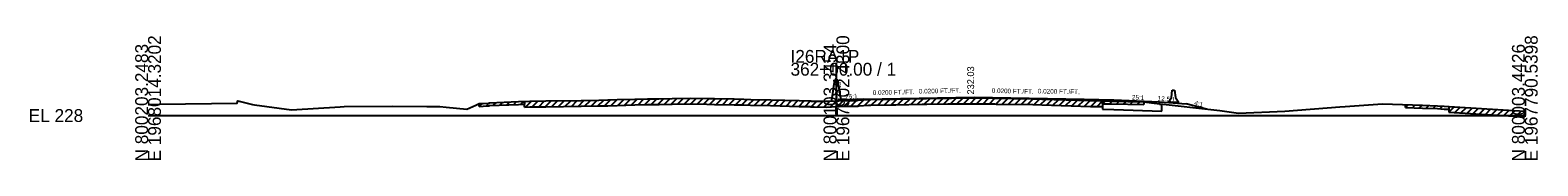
# Model space of a CAD drawing. Extents: x -26 to 304, y -10 to 7527.
# Drawn here: x -25.7 to 302.8, y 5990.3 to 6017.3 of the extents above; entities that cross this region are included whole.
import ezdxf

# ---------------------------------------------------------------- set-up
doc = ezdxf.new("R2010")
doc.units = 0
for name, color, linetype in [('Default', 7, 'Continuous'), ('RD_GPK_XS_Cell', 7, 'Continuous'), ('RD_XS_Base', 7, 'Continuous'), ('RD_XS_Box', 7, 'Continuous'), ('RD_XS_EarthShd', 7, 'Continuous'), ('RD_XS_ExGround', 7, 'Continuous'), ('RD_XS_ExPaveRet', 7, 'Continuous'), ('RD_XS_Misc_Line', 7, 'Continuous'), ('RD_XS_Pave', 7, 'Continuous'), ('RD_XS_PaveShd', 7, 'Continuous'), ('RD_XS_TX_Elev_EX', 7, 'Continuous'), ('RD_XS_TX_Elev_PR', 7, 'Continuous'), ('RD_XS_TX_Misc', 7, 'Continuous'), ('RD_XS_TX_MkPT', 7, 'Continuous'), ('RD_XS_TX_Profile', 7, 'Continuous'), ('RD_XS_TX_Station', 7, 'Continuous')]:
    doc.layers.add(name, color=color, linetype=linetype)

msp = doc.modelspace()

# ---------------------------------------------------------------- linework, layer by layer
at = {"layer": 'Default'}
for p, q in [((222.43, 6003.08), (223.01, 6003.92)), ((222.43, 6002.83), (222.43, 6003.08)), ((224.43, 6002.83), (222.43, 6002.83)), ((223.01, 6003.92), (223.18, 6005.5)), ((223.18, 6005.5), (223.68, 6005.5)), ((223.68, 6005.5), (223.85, 6003.92)), ((223.85, 6003.92), (224.43, 6003.08)), ((224.43, 6003.08), (224.43, 6002.83))]:
    msp.add_line(p, q, dxfattribs=at)
at = {"layer": 'RD_GPK_XS_Cell'}
for p, q in [((150, 6000), (150, 6011.49)), ((0, 6000), (150, 6000)), ((150, 6000), (300, 6000))]:
    msp.add_line(p, q, dxfattribs=at)
at = {"layer": 'RD_XS_Base'}
for p, q in [((150, 6003.19), (150, 6003.31)), ((220.43, 6002.43), (220.43, 6002.99)), ((220.93, 6002.41), (220.43, 6002.43)), ((220.93, 6000.93), (220.93, 6002.41)), ((208, 6001.41), (210.42, 6001.35)), ((210.42, 6001.35), (220.93, 6000.93))]:
    msp.add_line(p, q, dxfattribs=at)
at = {"layer": 'RD_XS_Box'}
for p in [(222.43, 6002.83), (230.67, 6001.41)]:
    msp.add_line(p, (226.18, 6002.53), dxfattribs=at)
at = {"layer": 'RD_XS_EarthShd'}
for p, q in [((149, 6003.33), (149.67, 6007.81)), ((150, 6007.81), (149.67, 6007.81)), ((150, 6007.81), (150.33, 6007.81)), ((151, 6003.33), (150.33, 6007.81)), ((220.43, 6002.99), (222.43, 6002.83))]:
    msp.add_line(p, q, dxfattribs=at)
at = {"layer": 'RD_XS_ExGround'}
msp.add_lwpolyline([(0, 6002.43), (0.97, 6002.44), (2.54, 6002.46), (19.43, 6002.68), (19.53, 6003.18), (22.76, 6002.44), (23.22, 6002.36), (31.22, 6001.28), (41.89, 6001.91), (42.73, 6001.96), (53.35, 6002.05), (60.75, 6001.98), (63.6, 6001.95), (64.95, 6001.82), (69.49, 6001.41), (71.44, 6002.26), (72.16, 6002.6), (72.99, 6002.64), (74.23, 6002.7), (74.41, 6002.8), (80.74, 6003.05), (83.18, 6003.14), (86.7, 6003.18), (94.34, 6003.26), (98.21, 6003.35), (100.16, 6003.39), (102.2, 6003.46), (106.07, 6003.59), (108.84, 6003.62), (111.33, 6003.64), (114.17, 6003.7), (118.15, 6003.79), (121.8, 6003.71), (123.44, 6003.68), (127.71, 6003.61), (129.82, 6003.57), (131.33, 6003.53), (135.68, 6003.41), (141.9, 6003.25), (144.41, 6003.18), (144.6, 6003.14), (145.19, 6003.13), (147.82, 6003.1), (150, 6003.19), (150.51, 6003.22), (151.78, 6003.27), (152.21, 6003.28), (154.41, 6003.31), (154.64, 6003.38), (156.92, 6003.48), (157.49, 6003.5), (161.97, 6003.57), (162.93, 6003.59), (168.63, 6003.72), (169.08, 6003.73), (169.66, 6003.74), (174.23, 6003.78), (174.66, 6003.78), (175.06, 6003.78), (181.03, 6003.83), (184.47, 6003.77), (184.83, 6003.76), (192.81, 6003.62), (194.77, 6003.56), (205.37, 6003.25), (209.92, 6003.15), (216.95, 6003), (219.2, 6002.73), (233.51, 6001.08), (237.6, 6000.5), (247.74, 6000.97), (259.67, 6001.92), (260.87, 6002), (268.99, 6002.55), (277.73, 6002.25), (281.01, 6002.15), (282.45, 6002.05), (284.65, 6001.91), (300, 6000.98)], dxfattribs=at)
at = {"layer": 'RD_XS_ExPaveRet'}
for p, q in [((72.16, 6001.97), (72.16, 6002.6)), ((74.41, 6002.18), (80.74, 6002.43)), ((80.74, 6002.43), (82, 6002.48)), ((82, 6001.85), (82, 6003.1)), ((82, 6003.1), (82, 6002.48)), ((208, 6003.19), (208, 6001.94)), ((208, 6002.57), (208, 6003.19)), ((208, 6002.57), (209.92, 6002.53)), ((209.92, 6002.53), (216.95, 6002.38)), ((216.95, 6003), (216.95, 6002.38)), ((274.01, 6001.75), (274.01, 6002.38)), ((72.16, 6001.97), (72.99, 6002.02)), ((72.99, 6002.02), (74.23, 6002.08)), ((74.23, 6002.08), (74.41, 6002.18)), ((274.01, 6001.75), (277.73, 6001.63)), ((277.73, 6001.63), (281.01, 6001.52)), ((281.01, 6001.52), (282.45, 6001.42)), ((282.45, 6001.42), (283.43, 6001.36)), ((283.43, 6001.99), (283.43, 6000.74)), ((300, 6000.98), (300, 5999.73))]:
    msp.add_line(p, q, dxfattribs=at)
for points in [[(82, 6001.85), (83.21, 6001.89), (86.71, 6001.93), (94.36, 6002.01), (98.24, 6002.1), (100.2, 6002.14), (102.24, 6002.21), (106.1, 6002.34), (108.85, 6002.37), (111.35, 6002.39), (114.19, 6002.45), (118.15, 6002.54), (121.77, 6002.46), (123.42, 6002.43), (127.69, 6002.36), (129.79, 6002.33), (131.3, 6002.28), (135.65, 6002.16), (141.87, 6002), (144.25, 6001.94), (144.45, 6001.89), (145.18, 6001.88), (147.84, 6001.85), (150.06, 6001.94), (150.56, 6001.97), (151.82, 6002.02), (152.24, 6002.03), (154.63, 6002.06), (154.87, 6002.14), (156.97, 6002.23), (157.52, 6002.25), (161.99, 6002.32), (162.95, 6002.34), (168.66, 6002.47), (169.1, 6002.48), (169.67, 6002.49), (174.24, 6002.53), (174.67, 6002.53), (175.06, 6002.53), (181.02, 6002.58), (184.45, 6002.52), (184.81, 6002.51), (192.78, 6002.37), (194.73, 6002.31), (205.34, 6002), (208, 6001.94)], [(283.43, 6000.74), (284.58, 6000.67), (300, 5999.73)]]:
    msp.add_lwpolyline(points, dxfattribs=at)
at = {"layer": 'RD_XS_Misc_Line'}
for p, q in [((72.16, 6001.97), (72.82, 6002.63)), ((73.66, 6002.05), (74.42, 6002.81)), ((75.16, 6002.21), (75.82, 6002.86)), ((76.66, 6002.27), (77.32, 6002.92)), ((78.17, 6002.33), (78.82, 6002.98)), ((79.67, 6002.39), (80.32, 6003.04)), ((81.17, 6002.44), (81.81, 6003.09)), ((82, 6003.04), (82.07, 6003.1)), ((82.24, 6001.86), (83.53, 6003.15)), ((83.69, 6001.9), (84.95, 6003.16)), ((85.12, 6001.91), (86.38, 6003.18)), ((86.55, 6001.93), (87.81, 6003.19)), ((87.98, 6001.94), (89.24, 6003.21)), ((89.41, 6001.96), (90.67, 6003.22)), ((90.83, 6001.97), (92.1, 6003.23)), ((92.26, 6001.99), (93.52, 6003.25)), ((93.69, 6002), (94.96, 6003.27)), ((95.13, 6002.02), (96.41, 6003.3)), ((96.58, 6002.06), (97.86, 6003.34)), ((98.02, 6002.09), (99.31, 6003.37)), ((99.47, 6002.13), (100.76, 6003.41)), ((100.93, 6002.17), (102.22, 6003.46)), ((102.39, 6002.21), (103.68, 6003.51)), ((103.85, 6002.26), (105.15, 6003.56)), ((105.32, 6002.31), (106.6, 6003.59)), ((106.77, 6002.35), (108.03, 6003.61)), ((108.2, 6002.36), (109.46, 6003.63)), ((109.62, 6002.38), (110.89, 6003.64)), ((111.05, 6002.39), (112.32, 6003.66)), ((112.49, 6002.41), (113.77, 6003.69)), ((113.93, 6002.44), (115.21, 6003.72)), ((115.38, 6002.47), (116.66, 6003.75)), ((116.82, 6002.51), (118.1, 6003.78)), ((118.27, 6002.53), (119.49, 6003.76)), ((119.65, 6002.51), (120.88, 6003.73)), ((121.04, 6002.48), (122.27, 6003.7)), ((122.43, 6002.45), (123.65, 6003.68)), ((123.82, 6002.43), (125.05, 6003.66)), ((125.21, 6002.4), (126.44, 6003.63)), ((126.6, 6002.38), (127.83, 6003.61)), ((127.99, 6002.36), (129.22, 6003.59)), ((129.38, 6002.33), (130.6, 6003.55)), ((130.76, 6002.3), (131.98, 6003.52)), ((132.14, 6002.26), (133.35, 6003.48)), ((133.51, 6002.22), (134.73, 6003.44)), ((134.89, 6002.19), (136.11, 6003.4)), ((136.27, 6002.15), (137.48, 6003.37)), ((137.64, 6002.11), (138.86, 6003.33)), ((139.02, 6002.07), (140.24, 6003.29)), ((140.4, 6002.04), (141.62, 6003.26)), ((141.78, 6002), (142.99, 6003.22)), ((143.15, 6001.96), (144.37, 6003.18)), ((144.49, 6001.89), (145.72, 6003.12)), ((145.89, 6001.87), (147.12, 6003.1)), ((147.28, 6001.85), (148.56, 6003.13)), ((148.73, 6001.89), (150.04, 6003.2)), ((150.21, 6001.95), (151.52, 6003.26)), ((151.69, 6002.01), (152.96, 6003.29)), ((153.13, 6002.04), (154.39, 6003.31)), ((154.56, 6002.06), (155.94, 6003.44)), ((156.11, 6002.19), (157.41, 6003.49)), ((157.58, 6002.25), (158.85, 6003.52)), ((159.02, 6002.27), (160.29, 6003.54)), ((160.46, 6002.3), (161.73, 6003.57)), ((161.89, 6002.32), (163.17, 6003.6)), ((163.34, 6002.35), (164.62, 6003.63)), ((164.79, 6002.38), (166.07, 6003.66)), ((166.23, 6002.42), (167.51, 6003.7)), ((167.68, 6002.45), (168.96, 6003.73)), ((169.13, 6002.48), (170.39, 6003.74)), ((170.55, 6002.49), (171.82, 6003.76)), ((171.98, 6002.51), (173.24, 6003.77)), ((173.41, 6002.52), (174.67, 6003.78)), ((174.84, 6002.53), (176.09, 6003.79)), ((176.26, 6002.54), (177.52, 6003.8)), ((177.68, 6002.55), (178.94, 6003.81)), ((179.11, 6002.57), (180.37, 6003.83)), ((180.54, 6002.58), (181.78, 6003.82)), ((181.94, 6002.56), (183.16, 6003.79)), ((183.33, 6002.54), (184.55, 6003.77)), ((184.71, 6002.51), (185.94, 6003.74)), ((186.1, 6002.49), (187.33, 6003.72)), ((187.49, 6002.46), (188.72, 6003.69)), ((188.88, 6002.44), (190.11, 6003.67)), ((190.27, 6002.41), (191.5, 6003.64)), ((191.66, 6002.39), (192.89, 6003.61)), ((193.04, 6002.36), (194.26, 6003.57)), ((194.42, 6002.32), (195.63, 6003.53)), ((195.79, 6002.28), (197.01, 6003.49)), ((197.17, 6002.24), (198.38, 6003.45)), ((198.54, 6002.2), (199.76, 6003.42)), ((199.92, 6002.16), (201.13, 6003.38)), ((201.29, 6002.12), (202.51, 6003.34)), ((202.67, 6002.08), (203.88, 6003.3)), ((204.04, 6002.04), (205.26, 6003.26)), ((205.42, 6002), (206.64, 6003.23)), ((206.8, 6001.97), (208, 6003.17)), ((208, 6002.57), (208.61, 6003.18)), ((209.5, 6002.54), (210.11, 6003.15)), ((211, 6002.5), (211.61, 6003.11)), ((212.5, 6002.47), (213.11, 6003.08)), ((214, 6002.44), (214.61, 6003.05)), ((215.5, 6002.41), (216.11, 6003.02)), ((274.01, 6001.75), (274.61, 6002.36)), ((275.51, 6001.7), (276.11, 6002.31)), ((277.01, 6001.65), (277.61, 6002.25)), ((278.51, 6001.6), (279.11, 6002.21)), ((280.01, 6001.56), (280.61, 6002.16)), ((281.51, 6001.49), (282.09, 6002.07)), ((283.43, 6000.75), (284.59, 6001.92)), ((284.75, 6000.66), (285.93, 6001.84)), ((286.08, 6000.57), (287.26, 6001.76)), ((287.41, 6000.49), (288.59, 6001.67)), ((288.75, 6000.41), (289.93, 6001.59)), ((290.08, 6000.33), (291.26, 6001.51)), ((291.41, 6000.25), (292.59, 6001.43)), ((292.75, 6000.17), (293.93, 6001.35)), ((294.08, 6000.09), (295.26, 6001.27)), ((295.41, 6000.01), (296.59, 6001.19)), ((296.74, 5999.93), (297.93, 6001.11)), ((298.08, 5999.84), (299.26, 6001.02)), ((299.41, 5999.76), (300, 6000.35))]:
    msp.add_line(p, q, dxfattribs=at)
at = {"layer": 'RD_XS_Pave'}
for p, q in [((156, 6003.55), (180, 6004.03)), ((180, 6004.03), (204, 6003.55)), ((204, 6003.55), (210.42, 6003.39))]:
    msp.add_line(p, q, dxfattribs=at)
at = {"layer": 'RD_XS_PaveShd'}
for p, q in [((156, 6003.55), (150, 6003.31)), ((210.42, 6003.39), (220.43, 6002.99))]:
    msp.add_line(p, q, dxfattribs=at)
at = {"layer": 'RD_XS_TX_Elev_PR'}
msp.add_line((208, 6003.19), (208, 6001.41), dxfattribs=at)
msp.add_lwpolyline([(150, 6003.19), (150.51, 6003.22), (151.78, 6003.27), (152.21, 6003.28), (154.41, 6003.31), (154.64, 6003.38), (156.92, 6003.48), (157.49, 6003.5), (161.97, 6003.57), (162.93, 6003.59), (168.63, 6003.72), (169.08, 6003.73), (169.66, 6003.74), (174.23, 6003.78), (174.66, 6003.78), (175.06, 6003.78), (181.03, 6003.83), (184.47, 6003.77), (184.83, 6003.76), (192.81, 6003.62), (194.77, 6003.56), (205.37, 6003.25), (208, 6003.19)], dxfattribs=at)

# ---------------------------------------------------------------- texts
at = {"layer": 'RD_GPK_XS_Cell'}
for s, p in [('N 800203.2483', (0, 5990)), ('E 1968014.3202', (2.8, 5990)), ('N 800103.3454', (150, 5990)), ('E 1967902.4300', (152.8, 5990)), ('N 800003.4426', (300, 5990)), ('E 1967790.5398', (302.8, 5990))]:
    msp.add_text(s, height=2.8, rotation=90, dxfattribs=at).set_placement(p)
for s, p in [('I26RA1P', (140, 6011.49)), ('362+00.00 / 1', (140, 6008.69)), ('EL 228', (-26, 5998.6))]:
    msp.add_text(s, height=2.8, dxfattribs=at).set_placement(p)
at = {"layer": 'RD_XS_TX_Elev_EX'}
msp.add_text('231.19', height=1, rotation=90, dxfattribs=at).set_placement((151, 6003.19))
at = {"layer": 'RD_XS_TX_Misc'}
msp.add_text('12.5:1', height=1, rotation=355.4297, dxfattribs=at).set_placement((219.97, 6003.28))
at = {"layer": 'RD_XS_TX_MkPT'}
for rotation, p in [(2.2906, (151.94, 6003.64)), (357.7112, (214.38, 6003.48))]:
    msp.add_text('25:1', height=1, rotation=rotation, dxfattribs=at).set_placement(p)
at = {"layer": 'RD_XS_TX_Profile'}
for s, rotation, p in [('0.0200 FT./FT.', 1.1458, (157.92, 6004.48)), ('0.0200 FT./FT.', 1.1458, (167.98, 6004.79)), ('0.0200 FT./FT.', 358.569, (183.84, 6004.94)), ('0.0200 FT./FT.', 358.8542, (193.89, 6004.83)), ('4:1', 345.9638, (227.9, 6002.32))]:
    msp.add_text(s, height=1, rotation=rotation, dxfattribs=at).set_placement(p)
at = {"layer": 'RD_XS_TX_Station'}
msp.add_text(' 232.03', height=1.5, rotation=90, dxfattribs=at).set_placement((180, 6004.03))

doc.saveas('drawing.dxf')
